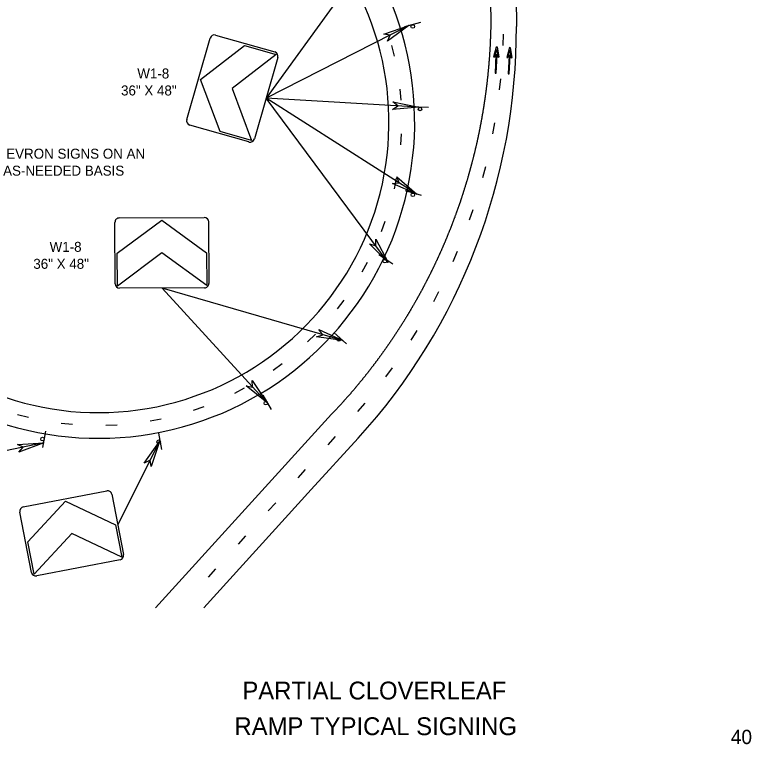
# Model space of a CAD drawing. Extents: x 582908 to 586040, y 1530940 to 1532988.
# Drawn here: x 585009 to 586040, y 1530991 to 1532013 of the extents above; entities that cross this region are included whole.
import ezdxf

# ---------------------------------------------------------------- set-up
doc = ezdxf.new("R2010")
doc.units = 0
for name, color, linetype in [('DirArrowsPavt', 7, 'Continuous'), ('LeaderLine_dp', 7, 'Continuous'), ('PMStripe6W', 7, 'Continuous'), ('PMStripe6W(10-30)', 7, 'Continuous'), ('PMStripe6Y', 7, 'Continuous'), ('SignPanel', 7, 'Continuous'), ('SignSupport', 7, 'Continuous'), ('TextLabel', 7, 'Continuous'), ('TextMisc', 7, 'Continuous'), ('TextShtNo', 7, 'Continuous')]:
    doc.layers.add(name, color=color, linetype=linetype)

# ---------------------------------------------------------------- blocks, each defined once
blk = doc.blocks.new('ArrTermPnt')
at = {"layer": 'LeaderLine_dp'}
for p, q in [((-0.1, 0), (-0.12, 0.02)), ((-0.12, 0.02), (0, 0)), ((0, 0), (-0.12, -0.02)), ((-0.12, -0.02), (-0.1, 0))]:
    blk.add_line(p, q, dxfattribs=at)

msp = doc.modelspace()

# ---------------------------------------------------------------- linework, layer by layer
at = {"layer": 'DirArrowsPavt'}
for p, q in [((585682.8, 1531967.4), (585679.1, 1531953.9)), ((585680.6, 1531953.5), (585683.5, 1531963.9)), ((585684.4, 1531967.4), (585682.8, 1531967.4)), ((585683.5, 1531963.9), (585685.3, 1531953.2)), ((585686.9, 1531953.5), (585684.4, 1531967.4)), ((585701.2, 1531966.6), (585697.5, 1531953)), ((585699, 1531952.6), (585701.9, 1531963)), ((585702.8, 1531966.5), (585701.2, 1531966.6)), ((585701.9, 1531963), (585703.7, 1531952.4)), ((585705.3, 1531952.7), (585702.8, 1531966.5)), ((585679.1, 1531953.9), (585680.6, 1531953.5)), ((585682.3, 1531956.5), (585681.2, 1531930.8)), ((585683.9, 1531956.4), (585682.3, 1531956.5)), ((585682.7, 1531930.7), (585683.9, 1531956.4)), ((585685.3, 1531953.2), (585686.9, 1531953.5)), ((585697.5, 1531953), (585699, 1531952.6)), ((585700.7, 1531955.7), (585699.6, 1531929.9)), ((585702.3, 1531955.6), (585700.7, 1531955.7)), ((585701.1, 1531929.8), (585702.3, 1531955.6)), ((585703.7, 1531952.4), (585705.3, 1531952.7)), ((585681.2, 1531930.8), (585682.7, 1531930.7)), ((585699.6, 1531929.9), (585701.1, 1531929.8))]:
    msp.add_line(p, q, dxfattribs=at)
at = {"layer": 'LeaderLine_dp'}
for p, q in [((585513.2, 1532106.3), (585360.5, 1531895.8)), ((585560.5, 1531997.4), (585360.5, 1531895.8)), ((585525.4, 1531985.7), (585560.5, 1531997.4)), ((585560.5, 1531997.4), (585530.3, 1531975.9)), ((585534.4, 1531984.1), (585525.4, 1531985.7)), ((585530.3, 1531975.9), (585534.4, 1531984.1)), ((585531.5, 1531665.6), (585360.5, 1531895.8)), ((585574.4, 1531883.1), (585360.5, 1531895.8)), ((585571.5, 1531761.3), (585360.5, 1531895.8)), ((585545.2, 1531884.9), (585538.2, 1531890.8)), ((585538.2, 1531890.8), (585574.4, 1531883.1)), ((585537.6, 1531879.8), (585545.2, 1531884.9)), ((585574.4, 1531883.1), (585537.6, 1531879.8)), ((585537.7, 1531776.4), (585546.8, 1531777.1)), ((585546.8, 1531777.1), (585543.6, 1531785.6)), ((585543.6, 1531785.6), (585571.5, 1531761.3)), ((585571.5, 1531761.3), (585537.7, 1531776.4)), ((585514.1, 1531689.1), (585514.1, 1531698.3)), ((585514.1, 1531698.3), (585531.5, 1531665.6)), ((585531.5, 1531665.6), (585505.3, 1531691.7)), ((585505.3, 1531691.7), (585514.1, 1531689.1)), ((585467.9, 1531556.3), (585214.8, 1531629.8)), ((585361.4, 1531469.3), (585214.8, 1531629.8)), ((585439.8, 1531564.4), (585434.3, 1531571.7)), ((585434.3, 1531571.7), (585467.9, 1531556.3)), ((585431.3, 1531561.2), (585439.8, 1531564.4)), ((585467.9, 1531556.3), (585431.3, 1531561.2)), ((585341.7, 1531490.9), (585340.8, 1531500)), ((585340.8, 1531500), (585361.4, 1531469.3)), ((585361.4, 1531469.3), (585332.7, 1531492.6)), ((585332.7, 1531492.6), (585341.7, 1531490.9)), ((585049.1, 1531412.7), (584837.2, 1531369)), ((585012.2, 1531410.7), (585049.1, 1531412.7)), ((585020.5, 1531406.8), (585012.2, 1531410.7)), ((585049.1, 1531412.7), (585014.4, 1531400)), ((585014.4, 1531400), (585020.5, 1531406.8)), ((585211.1, 1531414.7), (585152.7, 1531298.6)), ((585189.8, 1531384.5), (585211.1, 1531414.7)), ((585211.1, 1531414.7), (585199.6, 1531379.6)), ((585198, 1531388.6), (585189.8, 1531384.5)), ((585199.6, 1531379.6), (585198, 1531388.6))]:
    msp.add_line(p, q, dxfattribs=at)
at = {"layer": 'PMStripe6W'}
for p, q in [((585710.3, 1532156.5), (585711, 1531996.2)), ((585489.3, 1531419.3), (585423.8, 1531347.3)), ((585423.8, 1531347.3), (585273.2, 1531181.7))]:
    msp.add_line(p, q, dxfattribs=at)
for centre, radius, start, end in [((585125.6, 1531862.2), 407, 225.0711, 46.1803), ((584859.2, 1531992.4), 851.8, 317.7128, 0.254)]:
    msp.add_arc(centre, radius, start, end, dxfattribs=at)
at = {"layer": 'PMStripe6W(10-30)'}
for p, q in [((585692.3, 1531969.8), (585692.8, 1531985.4)), ((585540.4, 1531954.5), (585536.8, 1531969.7)), ((585687.5, 1531907.5), (585689.2, 1531923)), ((585549.5, 1531892.8), (585548.1, 1531908.3)), ((585678.1, 1531845.7), (585680.9, 1531861.1)), ((585549.4, 1531830.3), (585550.3, 1531845.9)), ((585664, 1531784.8), (585668, 1531799.9)), ((585540.1, 1531768.6), (585543.3, 1531783.9)), ((585645.5, 1531725.2), (585650.5, 1531739.9)), ((585521.9, 1531708.8), (585527.3, 1531723.5)), ((585622.5, 1531667.1), (585628.6, 1531681.4)), ((585495.2, 1531652.4), (585502.6, 1531666.1)), ((585595.2, 1531610.9), (585602.4, 1531624.7)), ((585460.4, 1531600.5), (585469.8, 1531613)), ((585418.5, 1531554.3), (585429.6, 1531565.2)), ((585563.7, 1531556.8), (585572, 1531570.1)), ((585370.2, 1531514.7), (585382.8, 1531523.9)), ((585528.3, 1531505.3), (585537.6, 1531518)), ((585316.6, 1531482.6), (585330.4, 1531489.9)), ((585489.2, 1531456.6), (585499.3, 1531468.5)), ((585258.9, 1531458.7), (585273.7, 1531463.9)), ((585012.6, 1531452.5), (585027.7, 1531448.7)), ((585073.8, 1531440.4), (585089.4, 1531438.8)), ((585136.2, 1531437.4), (585151.8, 1531438)), ((585198.4, 1531443.5), (585213.7, 1531446.5)), ((585447.3, 1531410.3), (585457.8, 1531421.8)), ((585405.4, 1531363.9), (585415.9, 1531375.4)), ((585363.5, 1531317.5), (585374.1, 1531329)), ((585321.7, 1531271.1), (585332.2, 1531282.7)), ((585279.8, 1531224.7), (585290.3, 1531236.3))]:
    msp.add_line(p, q, dxfattribs=at)
at = {"layer": 'PMStripe6Y'}
for p, q in [((585673.5, 1532343.3), (585675, 1531996.1)), ((585452.3, 1531452.9), (585205.7, 1531181.7))]:
    msp.add_line(p, q, dxfattribs=at)
msp.add_arc((585125.6, 1531862.2), 443, 225.021, 46.2304, dxfattribs=at)
for points in [[(585675, 1531996), (585675, 1531994.7), (585675, 1531993.3), (585675, 1531992), (585674.9, 1531990.6), (585674.9, 1531989.2), (585674.9, 1531987.9), (585674.8, 1531986.5), (585674.8, 1531985.1), (585674.7, 1531983.8), (585674.7, 1531982.4), (585674.6, 1531981), (585674.6, 1531979.7), (585674.5, 1531978.3), (585674.5, 1531977), (585674.4, 1531975.6), (585674.3, 1531974.2), (585674.3, 1531972.9), (585674.2, 1531971.5), (585674.1, 1531970.1), (585674.1, 1531968.8), (585674, 1531967.4), (585673.9, 1531966.1), (585673.9, 1531964.7), (585673.8, 1531963.3), (585673.7, 1531962), (585673.6, 1531960.6), (585673.5, 1531959.3), (585673.4, 1531957.9), (585673.3, 1531956.5), (585673.3, 1531955.2), (585673.2, 1531953.8), (585673.1, 1531952.5), (585673, 1531951.1), (585672.9, 1531949.7), (585672.8, 1531948.4), (585672.6, 1531947), (585672.5, 1531945.7), (585672.4, 1531944.3), (585672.3, 1531942.9), (585672.2, 1531941.6), (585672.1, 1531940.2), (585672, 1531938.9), (585671.8, 1531937.5), (585671.7, 1531936.2), (585671.6, 1531934.8), (585671.5, 1531933.4), (585671.3, 1531932.1), (585671.2, 1531930.7), (585671.1, 1531929.4), (585670.9, 1531928), (585670.8, 1531926.7), (585670.6, 1531925.3), (585670.5, 1531924), (585670.3, 1531922.6), (585670.2, 1531921.2), (585670, 1531919.9), (585669.9, 1531918.5), (585669.7, 1531917.2), (585669.6, 1531915.8), (585669.4, 1531914.5), (585669.2, 1531913.1), (585669.1, 1531911.8), (585668.9, 1531910.4), (585668.7, 1531909.1), (585668.6, 1531907.7), (585668.4, 1531906.4), (585668.2, 1531905), (585668, 1531903.7), (585667.9, 1531902.3), (585667.7, 1531901), (585667.5, 1531899.6), (585667.3, 1531898.3), (585667.1, 1531896.9), (585666.9, 1531895.6)], [(585666.9, 1531895.6), (585666.7, 1531894.2), (585666.5, 1531892.9), (585666.3, 1531891.6), (585666.1, 1531890.2), (585665.9, 1531888.9), (585665.7, 1531887.5), (585665.5, 1531886.2), (585665.3, 1531884.8), (585665.1, 1531883.5), (585664.9, 1531882.1), (585664.7, 1531880.8), (585664.4, 1531879.5), (585664.2, 1531878.1), (585664, 1531876.8), (585663.8, 1531875.4), (585663.5, 1531874.1), (585663.3, 1531872.7), (585663.1, 1531871.4), (585662.8, 1531870.1), (585662.6, 1531868.7), (585662.4, 1531867.4), (585662.1, 1531866.1), (585661.9, 1531864.7), (585661.6, 1531863.4), (585661.4, 1531862), (585661.1, 1531860.7), (585660.9, 1531859.4), (585660.6, 1531858), (585660.4, 1531856.7), (585660.1, 1531855.4), (585659.9, 1531854), (585659.6, 1531852.7), (585659.3, 1531851.4), (585659.1, 1531850), (585658.8, 1531848.7), (585658.5, 1531847.4), (585658.2, 1531846), (585658, 1531844.7), (585657.7, 1531843.4), (585657.4, 1531842.1), (585657.1, 1531840.7), (585656.8, 1531839.4), (585656.5, 1531838.1), (585656.3, 1531836.7), (585656, 1531835.4), (585655.7, 1531834.1), (585655.4, 1531832.8), (585655.1, 1531831.4), (585654.8, 1531830.1), (585654.5, 1531828.8), (585654.2, 1531827.5), (585653.8, 1531826.1), (585653.5, 1531824.8), (585653.2, 1531823.5), (585652.9, 1531822.2), (585652.6, 1531820.9), (585652.3, 1531819.5), (585652, 1531818.2), (585651.6, 1531816.9), (585651.3, 1531815.6), (585651, 1531814.3), (585650.6, 1531812.9), (585650.3, 1531811.6), (585650, 1531810.3), (585649.6, 1531809), (585649.3, 1531807.7), (585649, 1531806.4), (585648.6, 1531805.1), (585648.3, 1531803.7), (585647.9, 1531802.4), (585647.6, 1531801.1), (585647.2, 1531799.8), (585646.9, 1531798.5), (585646.5, 1531797.2)], [(585646.5, 1531797.2), (585646.2, 1531795.9), (585645.8, 1531794.6), (585645.4, 1531793.3), (585645.1, 1531792), (585644.7, 1531790.7), (585644.3, 1531789.4), (585644, 1531788), (585643.6, 1531786.7), (585643.2, 1531785.4), (585642.8, 1531784.1), (585642.5, 1531782.8), (585642.1, 1531781.5), (585641.7, 1531780.2), (585641.3, 1531778.9), (585640.9, 1531777.6), (585640.5, 1531776.3), (585640.1, 1531775), (585639.7, 1531773.7), (585639.3, 1531772.4), (585638.9, 1531771.1), (585638.5, 1531769.9), (585638.1, 1531768.6), (585637.7, 1531767.3), (585637.3, 1531766), (585636.9, 1531764.7), (585636.5, 1531763.4), (585636.1, 1531762.1), (585635.7, 1531760.8), (585635.2, 1531759.5), (585634.8, 1531758.2), (585634.4, 1531756.9), (585634, 1531755.7), (585633.6, 1531754.4), (585633.1, 1531753.1), (585632.7, 1531751.8), (585632.3, 1531750.5), (585631.8, 1531749.2), (585631.4, 1531748), (585630.9, 1531746.7), (585630.5, 1531745.4), (585630.1, 1531744.1), (585629.6, 1531742.8), (585629.2, 1531741.6), (585628.7, 1531740.3), (585628.3, 1531739), (585627.8, 1531737.7), (585627.3, 1531736.4), (585626.9, 1531735.2), (585626.4, 1531733.9), (585626, 1531732.6), (585625.5, 1531731.4), (585625, 1531730.1), (585624.6, 1531728.8), (585624.1, 1531727.5), (585623.6, 1531726.3), (585623.1, 1531725), (585622.7, 1531723.7), (585622.2, 1531722.5), (585621.7, 1531721.2), (585621.2, 1531719.9), (585620.7, 1531718.7), (585620.2, 1531717.4), (585619.7, 1531716.2), (585619.3, 1531714.9), (585618.8, 1531713.6), (585618.3, 1531712.4), (585617.8, 1531711.1), (585617.3, 1531709.9), (585616.8, 1531708.6), (585616.3, 1531707.4), (585615.7, 1531706.1), (585615.2, 1531704.8), (585614.7, 1531703.6), (585614.2, 1531702.3)], [(585614.2, 1531702.3), (585613.7, 1531701.1), (585613.2, 1531699.8), (585612.7, 1531698.6), (585612.1, 1531697.3), (585611.6, 1531696.1), (585611.1, 1531694.9), (585610.6, 1531693.6), (585610, 1531692.4), (585609.5, 1531691.1), (585609, 1531689.9), (585608.4, 1531688.6), (585607.9, 1531687.4), (585607.3, 1531686.2), (585606.8, 1531684.9), (585606.3, 1531683.7), (585605.7, 1531682.4), (585605.2, 1531681.2), (585604.6, 1531680), (585604.1, 1531678.7), (585603.5, 1531677.5), (585602.9, 1531676.3), (585602.4, 1531675), (585601.8, 1531673.8), (585601.3, 1531672.6), (585600.7, 1531671.4), (585600.1, 1531670.1), (585599.6, 1531668.9), (585599, 1531667.7), (585598.4, 1531666.5), (585597.8, 1531665.2), (585597.3, 1531664), (585596.7, 1531662.8), (585596.1, 1531661.6), (585595.5, 1531660.3), (585594.9, 1531659.1), (585594.4, 1531657.9), (585593.8, 1531656.7), (585593.2, 1531655.5), (585592.6, 1531654.3), (585592, 1531653.1), (585591.4, 1531651.8), (585590.8, 1531650.6), (585590.2, 1531649.4), (585589.6, 1531648.2), (585589, 1531647), (585588.4, 1531645.8), (585587.8, 1531644.6), (585587.1, 1531643.4), (585586.5, 1531642.2), (585585.9, 1531641), (585585.3, 1531639.8), (585584.7, 1531638.6), (585584.1, 1531637.4), (585583.4, 1531636.2), (585582.8, 1531635), (585582.2, 1531633.8), (585581.6, 1531632.6), (585580.9, 1531631.4), (585580.3, 1531630.2), (585579.7, 1531629), (585579, 1531627.8), (585578.4, 1531626.6), (585577.7, 1531625.5), (585577.1, 1531624.3), (585576.5, 1531623.1), (585575.8, 1531621.9), (585575.2, 1531620.7), (585574.5, 1531619.5), (585573.9, 1531618.4), (585573.2, 1531617.2), (585572.5, 1531616), (585571.9, 1531614.8), (585571.2, 1531613.6), (585570.6, 1531612.5)], [(585570.6, 1531612.5), (585569.9, 1531611.3), (585569.2, 1531610.1), (585568.6, 1531608.9), (585567.9, 1531607.8), (585567.2, 1531606.6), (585566.5, 1531605.4), (585565.9, 1531604.3), (585565.2, 1531603.1), (585564.5, 1531601.9), (585563.8, 1531600.8), (585563.1, 1531599.6), (585562.5, 1531598.5), (585561.8, 1531597.3), (585561.1, 1531596.1), (585560.4, 1531595), (585559.7, 1531593.8), (585559, 1531592.7), (585558.3, 1531591.5), (585557.6, 1531590.4), (585556.9, 1531589.2), (585556.2, 1531588.1), (585555.5, 1531586.9), (585554.8, 1531585.8), (585554.1, 1531584.6), (585553.4, 1531583.5), (585552.7, 1531582.3), (585552, 1531581.2), (585551.2, 1531580), (585550.5, 1531578.9), (585549.8, 1531577.8), (585549.1, 1531576.6), (585548.4, 1531575.5), (585547.6, 1531574.4), (585546.9, 1531573.2), (585546.2, 1531572.1), (585545.4, 1531571), (585544.7, 1531569.8), (585544, 1531568.7), (585543.2, 1531567.6), (585542.5, 1531566.4), (585541.8, 1531565.3), (585541, 1531564.2), (585540.3, 1531563.1), (585539.5, 1531561.9), (585538.8, 1531560.8), (585538, 1531559.7), (585537.3, 1531558.6), (585536.5, 1531557.5), (585535.8, 1531556.4), (585535, 1531555.2), (585534.3, 1531554.1), (585533.5, 1531553), (585532.7, 1531551.9), (585532, 1531550.8), (585531.2, 1531549.7), (585530.4, 1531548.6), (585529.7, 1531547.5), (585528.9, 1531546.4), (585528.1, 1531545.3), (585527.3, 1531544.2), (585526.6, 1531543.1), (585525.8, 1531542), (585525, 1531540.9), (585524.2, 1531539.8), (585523.4, 1531538.7), (585522.7, 1531537.6), (585521.9, 1531536.5), (585521.1, 1531535.4), (585520.3, 1531534.3), (585519.5, 1531533.2), (585518.7, 1531532.2), (585517.9, 1531531.1), (585517.1, 1531530), (585516.3, 1531528.9)], [(585516.3, 1531528.9), (585515.5, 1531527.8), (585514.7, 1531526.8), (585513.9, 1531525.7), (585513.1, 1531524.6), (585512.3, 1531523.5), (585511.5, 1531522.5), (585510.7, 1531521.4), (585509.8, 1531520.3), (585509, 1531519.2), (585508.2, 1531518.2), (585507.4, 1531517.1), (585506.6, 1531516), (585505.7, 1531515), (585504.9, 1531513.9), (585504.1, 1531512.9), (585503.3, 1531511.8), (585502.4, 1531510.7), (585501.6, 1531509.7), (585500.8, 1531508.6), (585499.9, 1531507.6), (585499.1, 1531506.5), (585498.3, 1531505.5), (585497.4, 1531504.4), (585496.6, 1531503.4), (585495.7, 1531502.3), (585494.9, 1531501.3), (585494, 1531500.3), (585493.2, 1531499.2), (585492.3, 1531498.2), (585491.5, 1531497.1), (585490.6, 1531496.1), (585489.8, 1531495.1), (585488.9, 1531494), (585488.1, 1531493), (585487.2, 1531492), (585486.3, 1531490.9), (585485.5, 1531489.9), (585484.6, 1531488.9), (585483.7, 1531487.8), (585482.9, 1531486.8), (585482, 1531485.8), (585481.1, 1531484.8), (585480.3, 1531483.8), (585479.4, 1531482.7), (585478.5, 1531481.7), (585477.6, 1531480.7), (585476.7, 1531479.7), (585475.9, 1531478.7), (585475, 1531477.7), (585474.1, 1531476.7), (585473.2, 1531475.7), (585472.3, 1531474.7), (585471.4, 1531473.7), (585470.5, 1531472.7), (585469.6, 1531471.6), (585468.7, 1531470.7), (585467.8, 1531469.7), (585466.9, 1531468.7), (585466, 1531467.7), (585465.1, 1531466.7), (585464.2, 1531465.7), (585463.3, 1531464.7), (585462.4, 1531463.7), (585461.5, 1531462.7), (585460.6, 1531461.7), (585459.7, 1531460.7), (585458.8, 1531459.8), (585457.9, 1531458.8), (585456.9, 1531457.8), (585456, 1531456.8), (585455.1, 1531455.8), (585454.2, 1531454.9), (585452.3, 1531452.9)]]:
    msp.add_spline(points, degree=3, dxfattribs=at)
at = {"layer": 'SignPanel'}
for p, q in [((585268.9, 1531922.1), (585330.5, 1531969.5)), ((585330.5, 1531969.5), (585374.8, 1531956.8)), ((585374.8, 1531956.8), (585313.2, 1531909.4)), ((585296, 1531849.3), (585268.9, 1531922.1)), ((585313.2, 1531909.4), (585340.3, 1531836.5)), ((585340.3, 1531836.5), (585296, 1531849.3)), ((585152.1, 1531678.7), (585214.5, 1531725.1)), ((585214.5, 1531725.1), (585277.2, 1531679.2)), ((585152.3, 1531632.6), (585152.1, 1531678.7)), ((585214.6, 1531679), (585152.3, 1531632.6)), ((585277.4, 1531633.1), (585214.6, 1531679)), ((585277.2, 1531679.2), (585277.4, 1531633.1)), ((585026.9, 1531274.1), (585079.5, 1531331.3)), ((585079.5, 1531331.3), (585149.7, 1531298)), ((585149.7, 1531298), (585158.5, 1531252.7)), ((585088.3, 1531286), (585035.7, 1531228.8)), ((585158.5, 1531252.7), (585088.3, 1531286)), ((585035.7, 1531228.8), (585026.9, 1531274.1))]:
    msp.add_line(p, q, dxfattribs=at)
for points in [[(585289.9, 1531984.3), (585372.7, 1531960.6)], [(585249.5, 1531865.8), (585282.3, 1531980.1)], [(585376.9, 1531953), (585344.1, 1531838.7)], [(585336.5, 1531834.4), (585253.7, 1531858.2)], [(585155, 1531728), (585273.9, 1531728.4)], [(585149.2, 1531635.7), (585148.9, 1531721.8)], [(585280.1, 1531722.3), (585280.4, 1531636.1)], [(585274.3, 1531630), (585155.3, 1531629.5)], [(585020.5, 1531323), (585137.3, 1531345.7)], [(585144.5, 1531340.8), (585160.9, 1531256.3)], [(585032.1, 1531231.2), (585015.7, 1531315.8)], [(585156.1, 1531249.1), (585039.3, 1531226.4)]]:
    msp.add_lwpolyline(points, dxfattribs=at)
for centre, start, end in [((585288.2, 1531978.4), 74.0069, 164.0069), ((585371, 1531954.7), 344.0069, 74.0069), ((585255.4, 1531864.1), 164.0069, 254.0069), ((585338.2, 1531840.3), 254.0069, 344.0069), ((585155, 1531721.8), 90.2084, 180.2084), ((585274, 1531722.3), 0.2084, 90.2084), ((585155.3, 1531635.7), 180.2084, 270.2084), ((585274.3, 1531636.1), 270.2084, 0.2084), ((585138.5, 1531339.7), 10.9993, 100.9993), ((585021.7, 1531317), 100.9993, 190.9993), ((585154.9, 1531255.1), 280.9993, 10.9993), ((585038.1, 1531232.4), 190.9993, 280.9993)]:
    msp.add_arc(centre, 6.15, start, end, dxfattribs=at)
at = {"layer": 'SignSupport'}
for p, q in [((585576.5, 1532001.9), (585554.1, 1531995.6)), ((585587.7, 1531882.8), (585564.5, 1531883.4)), ((585577.9, 1531759.5), (585555.5, 1531765.8)), ((585537.9, 1531663.1), (585518.5, 1531676.1)), ((585472.9, 1531551.8), (585455.5, 1531567.4)), ((585368.3, 1531459.8), (585356.3, 1531479.8)), ((585048, 1531406.2), (585051.9, 1531429.1)), ((585214.7, 1531403.6), (585210.3, 1531426.4))]:
    msp.add_line(p, q, dxfattribs=at)
for centre in [(585565.9, 1531996.3), (585576, 1531880.6), (585566, 1531760.3), (585526.8, 1531667.5), (585462.5, 1531557.7), (585360.2, 1531468.5), (585047.5, 1531418.1), (585210.1, 1531414.5)]:
    msp.add_circle(centre, 2.49, dxfattribs=at)

# ---------------------------------------------------------------- block references
at = {"layer": 'TextLabel'}
for p, xscale, yscale, rotation in [((585560.5, 1531997.4), 2.0416666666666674, 1.9442318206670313, 26.925427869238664), ((585467.9, 1531556.3), 2.041666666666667, 1.9442318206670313, -16.189425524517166), ((585361.4, 1531469.3), 2.0416666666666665, 1.9442318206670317, -47.59235154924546), ((585049.1, 1531412.7), 2.041666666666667, 1.9442318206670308, 11.660681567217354), ((585211.1, 1531414.7), 2.041666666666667, 1.9442318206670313, 63.3113532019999)]:
    msp.add_blockref('ArrTermPnt', p, dxfattribs=dict(at, xscale=xscale, yscale=yscale, rotation=rotation))

# ---------------------------------------------------------------- texts
for s, p in [('W1-8', (585180.2, 1531923.4)), ('36" X 48"', (585157.4, 1531899.6)), ('CHEVRON SIGNS ON AN', (584969.6, 1531811)), ('AS-NEEDED BASIS', (584992.3, 1531787.2)), ('W1-8', (585057.4, 1531680.5)), ('36" X 48"', (585034.6, 1531656.7))]:
    msp.add_text(s, height=14, dxfattribs=at).set_placement(p)
at = {"layer": 'TextMisc'}
for s, p in [('   PARTIAL CLOVERLEAF   ', (585299.4, 1531053.3)), ('  RAMP TYPICAL SIGNING  ', (585297.6, 1531003.3))]:
    msp.add_text(s, height=25, rotation=360, dxfattribs=at).set_placement(p)
at = {"layer": 'TextShtNo'}
msp.add_text('40', height=20, rotation=360, dxfattribs=at).set_placement((586011.2, 1530990.8))

doc.saveas('drawing.dxf')
